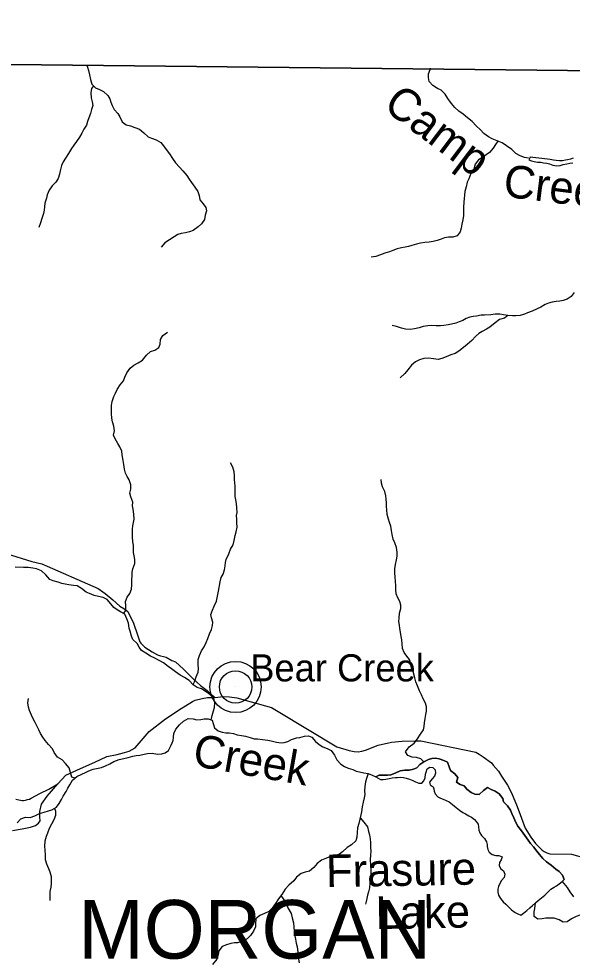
# Model space of a CAD drawing. Extents: x 1624196 to 2029251, y 146837 to 440034.
# Drawn here: x 1804212 to 1812706, y 335419 to 349890 of the extents above; entities that cross this region are included whole.
import ezdxf

# ---------------------------------------------------------------- set-up
doc = ezdxf.new("R2010")
doc.units = 0
for name, color, linetype in [('GM_X_Adjacent_County', 7, 'Continuous'), ('GM_X_County', 7, 'Continuous'), ('GM_X_County_Road', 7, 'Continuous'), ('GM_X_Major_River', 7, 'Continuous'), ('GM_X_Minor_Lake', 7, 'Continuous'), ('GM_X_Minor_Lake_Text', 7, 'Continuous'), ('GM_X_Minor_River', 7, 'Continuous'), ('GM_X_Minor_River_Text', 7, 'Continuous'), ('GM_X_Township', 7, 'Continuous'), ('GM_X_Township_Road', 7, 'Continuous'), ('GM_X_Township_Text', 7, 'Continuous'), ('GM_X_Unincorporated', 7, 'Continuous'), ('GM_X_Unincorporated_Location', 7, 'Continuous'), ('GM_X_Unincorporated_Text', 7, 'Continuous')]:
    doc.layers.add(name, color=color, linetype=linetype)

msp = doc.modelspace()

# ---------------------------------------------------------------- linework, layer by layer
at = {"layer": 'GM_X_Adjacent_County'}
msp.add_lwpolyline([(1826336, 348649), (1819510, 348957), (1818598, 348960), (1813935, 349079), (1813587, 349087), (1795056, 349285), (1795014, 349286), (1790774, 349462), (1789921, 349486), (1783877, 349656), (1782423, 349710), (1777594, 349890)], dxfattribs=at)
at = {"layer": 'GM_X_County'}
msp.add_lwpolyline([(1777594, 349890), (1782423, 349710), (1783877, 349656), (1789921, 349486), (1790774, 349462), (1795014, 349286), (1795056, 349285), (1813587, 349087), (1813935, 349079), (1818598, 348960), (1819510, 348957), (1826336, 348649)], dxfattribs=at)
at = {"layer": 'GM_X_County_Road'}
for points in [[(1804164, 337906), (1804212, 337895), (1804262, 337886), (1804282, 337886), (1804313, 337891), (1804346, 337899), (1804375, 337909), (1804399, 337921), (1804532, 337993), (1804670, 338059), (1804808, 338144), (1804932, 338274), (1805160, 338376), (1805380, 338477), (1805560, 338561), (1805721, 338591), (1805836, 338623), (1805906, 338644), (1805997, 338693), (1806212, 338946), (1806463, 339141), (1806706, 339298), (1806876, 339407), (1806917, 339425), (1807027, 339455), (1807110, 339466), (1807222, 339468)], [(1807222, 339468), (1807353, 339481), (1807445, 339478), (1807559, 339463), (1808092, 339313), (1808194, 339255), (1809094, 338711), (1809282, 338654), (1809358, 338640), (1809422, 338636), (1809479, 338642), (1809532, 338660), (1809726, 338737), (1809931, 338780), (1810096, 338796), (1810305, 338805), (1810383, 338802), (1811226, 338629), (1811277, 338600), (1811338, 338557), (1811467, 338465), (1811496, 338431), (1811575, 338339), (1811622, 338258), (1811712, 338122), (1811777, 338003), (1811862, 337793), (1811931, 337616), (1811983, 337459), (1812071, 337325), (1812144, 337226), (1812244, 337122), (1812279, 337101), (1812318, 337080), (1812364, 337068), (1812697, 337061), (1812914, 337000)], [(1804115, 337425), (1804263, 337452), (1804391, 337479), (1804466, 337502), (1804514, 337536), (1804538, 337574), (1804535, 337636), (1804532, 337718), (1804561, 337832), (1804646, 337953), (1804808, 338144)]]:
    msp.add_lwpolyline(points, dxfattribs=at)
at = {"layer": 'GM_X_Major_River'}
msp.add_lwpolyline([(1812724, 347749), (1812680, 347737), (1812634, 347726), (1812604, 347722), (1812556, 347712), (1812510, 347711), (1812460, 347715), (1812420, 347719), (1812368, 347728), (1812326, 347734), (1812280, 347741), (1812240, 347745), (1812196, 347749), (1812148, 347754), (1812102, 347760), (1812062, 347764), (1812039, 347727), (1812083, 347710), (1812125, 347698), (1812175, 347689), (1812223, 347687), (1812267, 347681), (1812317, 347672), (1812359, 347662), (1812409, 347645), (1812471, 347635), (1812521, 347640), (1812569, 347652), (1812623, 347664), (1812672, 347673), (1812718, 347681)], dxfattribs=at)
at = {"layer": 'GM_X_Minor_Lake'}
for points in [[(1812553, 336643), (1812581, 336673), (1812560, 336737), (1812506, 336798), (1812454, 336834), (1812385, 336891), (1812311, 336944), (1812258, 336998), (1812204, 337055), (1812163, 337109), (1812111, 337174), (1812067, 337224), (1812032, 337277), (1811929, 337422), (1811872, 337492), (1811844, 337549), (1811809, 337619), (1811781, 337687), (1811760, 337738), (1811716, 337804), (1811653, 337867), (1811643, 337917), (1811586, 337988), (1811524, 338028), (1811462, 338057), (1811406, 338087), (1811344, 338038), (1811277, 337978), (1811213, 337981), (1811157, 338009), (1811090, 338060), (1811046, 338112), (1810986, 338133), (1810931, 338167), (1810949, 338237), (1810904, 338294), (1810840, 338348), (1810820, 338405), (1810791, 338473), (1810735, 338502), (1810667, 338524), (1810609, 338537), (1810551, 338531), (1810501, 338516), (1810431, 338482), (1810370, 338438), (1810322, 338387), (1810272, 338365), (1810203, 338352), (1810135, 338350), (1810065, 338343), (1809991, 338305), (1809922, 338278), (1809870, 338276), (1809798, 338277), (1809742, 338275), (1809692, 338252)], [(1809692, 338252), (1809764, 338211), (1809806, 338211), (1809848, 338214), (1809898, 338226), (1809944, 338234), (1809994, 338239), (1810024, 338241), (1810070, 338242), (1810118, 338240), (1810160, 338230), (1810210, 338213), (1810258, 338193), (1810302, 338174), (1810352, 338152), (1810398, 338154), (1810430, 338187), (1810451, 338233), (1810457, 338289), (1810463, 338323), (1810482, 338371), (1810522, 338399), (1810568, 338395), (1810604, 338356), (1810609, 338306), (1810593, 338260), (1810557, 338218), (1810518, 338169), (1810526, 338129), (1810570, 338098), (1810581, 338064), (1810587, 338030), (1810605, 337988), (1810646, 337941), (1810686, 337923), (1810728, 337906), (1810774, 337886), (1810818, 337866), (1810871, 337825), (1810923, 337779), (1810975, 337740), (1811027, 337704), (1811070, 337679), (1811118, 337653), (1811162, 337628), (1811208, 337596), (1811234, 337566), (1811261, 337523), (1811269, 337481), (1811274, 337433), (1811288, 337389), (1811316, 337349), (1811361, 337304), (1811393, 337250), (1811399, 337208), (1811402, 337178), (1811412, 337133), (1811434, 337093), (1811479, 337059), (1811533, 337042), (1811581, 337040), (1811631, 337019), (1811617, 336977), (1811590, 336932), (1811588, 336888), (1811608, 336843), (1811651, 336805), (1811673, 336755), (1811664, 336705), (1811620, 336657), (1811594, 336609), (1811575, 336567), (1811565, 336525), (1811564, 336479), (1811574, 336431), (1811604, 336380), (1811647, 336332), (1811689, 336292), (1811735, 336249), (1811776, 336209), (1811830, 336168), (1811870, 336146), (1811916, 336123), (1811960, 336157), (1812010, 336199), (1812055, 336238), (1812097, 336276), (1812144, 336314), (1812186, 336350), (1812236, 336391), (1812287, 336433), (1812327, 336471), (1812380, 336522), (1812428, 336554), (1812468, 336578), (1812509, 336605), (1812553, 336643)]]:
    msp.add_lwpolyline(points, dxfattribs=at)
at = {"layer": 'GM_X_Minor_River'}
for points in [[(1805251, 349186), (1805264, 349147), (1805280, 349095), (1805297, 349032), (1805311, 348960), (1805334, 348888), (1805388, 348833), (1805448, 348805), (1805513, 348772), (1805577, 348715), (1805609, 348663), (1805624, 348613), (1805646, 348560), (1805675, 348500), (1805733, 348438), (1805760, 348383), (1805798, 348311), (1805861, 348262), (1805925, 348246), (1805993, 348223), (1806065, 348194), (1806131, 348138), (1806196, 348079), (1806248, 348059), (1806322, 348032), (1806390, 347993), (1806431, 347941), (1806475, 347884), (1806522, 347818), (1806570, 347745), (1806619, 347679), (1806677, 347614), (1806728, 347558), (1806790, 347487), (1806827, 347429), (1806861, 347378), (1806912, 347306), (1806958, 347237), (1806979, 347177), (1806992, 347111), (1807042, 347048), (1807080, 346992), (1807093, 346941), (1807073, 346875), (1807060, 346809), (1807015, 346742), (1806963, 346698), (1806890, 346640), (1806834, 346617), (1806770, 346605), (1806706, 346596), (1806653, 346578), (1806597, 346541), (1806523, 346495), (1806454, 346448), (1806395, 346382)], [(1812038, 347753), (1811974, 347763), (1811906, 347784), (1811840, 347824), (1811778, 347883), (1811699, 347938), (1811631, 347986), (1811557, 348017), (1811480, 348046), (1811420, 348078), (1811352, 348131), (1811301, 348188), (1811231, 348246), (1811170, 348313), (1811102, 348372), (1811034, 348426), (1810967, 348471), (1810905, 348529), (1810854, 348592), (1810800, 348665), (1810759, 348731), (1810693, 348796), (1810641, 348820), (1810568, 348869), (1810512, 348927), (1810499, 348990), (1810501, 349044), (1810528, 349114), (1810529, 349134)], [(1805360, 348861), (1805328, 348820), (1805315, 348754), (1805322, 348679), (1805336, 348617), (1805345, 348557), (1805325, 348497), (1805310, 348439), (1805286, 348371), (1805267, 348313), (1805251, 348259), (1805210, 348195), (1805181, 348137), (1805145, 348072), (1805096, 348006), (1805056, 347952), (1805019, 347898), (1804975, 347824), (1804930, 347753), (1804893, 347695), (1804869, 347639), (1804846, 347557), (1804838, 347505), (1804815, 347439), (1804780, 347381), (1804724, 347324), (1804679, 347260), (1804647, 347188), (1804634, 347134), (1804613, 347060), (1804603, 347002), (1804600, 346952), (1804590, 346900), (1804567, 346826), (1804545, 346756), (1804520, 346688)], [(1811564, 348014), (1811531, 347961), (1811496, 347905), (1811438, 347840), (1811387, 347800), (1811319, 347754), (1811267, 347723), (1811218, 347657), (1811197, 347583), (1811153, 347515), (1811118, 347433), (1811093, 347382), (1811077, 347312), (1811060, 347238), (1811054, 347184), (1811047, 347133), (1811043, 347077), (1811040, 346999), (1811039, 346869), (1811026, 346805), (1811014, 346737), (1811003, 346677), (1810989, 346617), (1810940, 346557), (1810872, 346538), (1810808, 346536), (1810747, 346525), (1810693, 346505), (1810633, 346488), (1810573, 346470), (1810513, 346463), (1810447, 346453), (1810378, 346444), (1810316, 346432), (1810246, 346411), (1810196, 346393), (1810142, 346383), (1810087, 346376), (1810019, 346358), (1809955, 346335), (1809903, 346313), (1809830, 346292), (1809762, 346268), (1809690, 346239), (1809622, 346231)], [(1812738, 345687), (1812690, 345625), (1812629, 345587), (1812569, 345564), (1812519, 345556), (1812463, 345551), (1812399, 345541), (1812342, 345524), (1812292, 345504), (1812226, 345464), (1812171, 345437), (1812093, 345399), (1812023, 345374), (1811973, 345356), (1811906, 345335), (1811840, 345329), (1811790, 345328), (1811718, 345332), (1811652, 345347), (1811594, 345355), (1811524, 345354), (1811458, 345345), (1811358, 345341), (1811308, 345338), (1811239, 345324), (1811189, 345317), (1811133, 345307), (1811081, 345288), (1811029, 345260), (1810974, 345236), (1810920, 345215), (1810854, 345199), (1810804, 345190), (1810734, 345180), (1810684, 345175), (1810618, 345175), (1810547, 345182), (1810493, 345178), (1810419, 345165), (1810359, 345147), (1810287, 345130), (1810217, 345122), (1810147, 345127), (1810087, 345139), (1810007, 345166), (1809941, 345183)], [(1811717, 345333), (1811666, 345291), (1811591, 345273), (1811523, 345224), (1811444, 345154), (1811392, 345123), (1811324, 345091), (1811273, 345060), (1811223, 345012), (1811166, 344952), (1811092, 344891), (1811015, 344825), (1810964, 344786), (1810910, 344750), (1810846, 344728), (1810774, 344699), (1810707, 344673), (1810647, 344660), (1810579, 344670), (1810499, 344677), (1810427, 344672), (1810363, 344654), (1810300, 344625), (1810238, 344573), (1810183, 344501), (1810137, 344444), (1810064, 344376)], [(1805820, 340757), (1805852, 340806), (1805855, 340878), (1805847, 340944), (1805874, 341008), (1805917, 341064), (1805941, 341134), (1805948, 341200), (1805946, 341274), (1805949, 341340), (1805951, 341392), (1805964, 341444), (1805993, 341524), (1805993, 341586), (1805984, 341642), (1805972, 341693), (1805970, 341743), (1805971, 341809), (1805962, 341861), (1805956, 341933), (1805957, 341999), (1805955, 342053), (1805964, 342103), (1805974, 342157), (1805981, 342209), (1805977, 342282), (1805968, 342358), (1805954, 342412), (1805961, 342470), (1805931, 342549), (1805916, 342607), (1805933, 342665), (1805933, 342735), (1805904, 342809), (1805874, 342860), (1805847, 342912), (1805833, 342972), (1805826, 343048), (1805814, 343107), (1805799, 343197), (1805793, 343249), (1805762, 343317), (1805730, 343370), (1805691, 343440), (1805667, 343496), (1805678, 343564), (1805671, 343637), (1805649, 343699), (1805640, 343759), (1805636, 343827), (1805635, 343893), (1805635, 343954), (1805646, 344012), (1805671, 344090), (1805693, 344141), (1805722, 344199), (1805766, 344269), (1805817, 344333), (1805837, 344385), (1805872, 344455), (1805921, 344528), (1805975, 344574), (1806042, 344610), (1806112, 344649), (1806171, 344723), (1806233, 344784), (1806300, 344804), (1806360, 344841), (1806380, 344893), (1806387, 344965), (1806422, 345027), (1806492, 345077)], [(1806886, 339666), (1806906, 339707), (1806936, 339783), (1806965, 339859), (1806970, 339911), (1806966, 339969), (1806965, 340049), (1806985, 340115), (1807016, 340187), (1807055, 340245), (1807087, 340315), (1807112, 340375), (1807140, 340447), (1807169, 340513), (1807184, 340575), (1807190, 340625), (1807171, 340691), (1807159, 340745), (1807186, 340809), (1807210, 340869), (1807245, 340945), (1807262, 341023), (1807276, 341101), (1807302, 341245), (1807320, 341309), (1807347, 341361), (1807369, 341431), (1807378, 341489), (1807382, 341539), (1807395, 341589), (1807435, 341675), (1807462, 341744), (1807501, 341812), (1807519, 341880), (1807534, 341956), (1807549, 342010), (1807561, 342084), (1807560, 342150), (1807556, 342207), (1807555, 342261), (1807563, 342311), (1807556, 342379), (1807552, 342445), (1807543, 342503), (1807535, 342557), (1807534, 342610), (1807534, 342666), (1807533, 342716), (1807522, 342816), (1807522, 342878), (1807519, 342936), (1807497, 343005), (1807462, 343073)], [(1810431, 338482), (1810383, 338524), (1810315, 338545), (1810249, 338554), (1810183, 338576), (1810150, 338633), (1810206, 338708), (1810279, 338766), (1810332, 338834), (1810380, 338903), (1810425, 338973), (1810433, 339023), (1810438, 339079), (1810449, 339145), (1810461, 339207), (1810470, 339257), (1810472, 339325), (1810455, 339380), (1810421, 339450), (1810392, 339508), (1810362, 339569), (1810333, 339645), (1810307, 339711), (1810292, 339768), (1810273, 339848), (1810247, 339918), (1810230, 339985), (1810210, 340049), (1810169, 340105), (1810125, 340158), (1810104, 340222), (1810096, 340292), (1810089, 340352), (1810083, 340405), (1810070, 340473), (1810060, 340527), (1810053, 340581), (1810047, 340633), (1810048, 340685), (1810058, 340763), (1810075, 340835), (1810077, 340885), (1810060, 340944), (1810030, 341000), (1810005, 341058), (1809997, 341129), (1809998, 341185), (1809993, 341255), (1809987, 341315), (1809984, 341383), (1809982, 341443), (1809993, 341509), (1810009, 341581), (1810020, 341641), (1810022, 341699), (1810011, 341772), (1809982, 341844), (1809960, 341900), (1809941, 341969), (1809933, 342035), (1809920, 342101), (1809904, 342155), (1809887, 342206), (1809865, 342276), (1809860, 342348), (1809856, 342402), (1809855, 342456), (1809849, 342516), (1809844, 342567), (1809832, 342631), (1809797, 342703), (1809779, 342759), (1809772, 342814)], [(1807166, 339124), (1807178, 339194), (1807200, 339264), (1807213, 339314), (1807221, 339384), (1807206, 339456), (1807146, 339515), (1807085, 339557), (1807015, 339602), (1806949, 339621), (1806887, 339665), (1806824, 339730), (1806754, 339777), (1806690, 339811), (1806619, 339860), (1806555, 339906), (1806503, 339943), (1806430, 339998), (1806364, 340036), (1806288, 340075), (1806234, 340105), (1806161, 340148), (1806095, 340191), (1806059, 340241), (1806026, 340296), (1805964, 340358), (1805941, 340412), (1805919, 340485), (1805904, 340535), (1805895, 340607), (1805869, 340678), (1805838, 340746), (1805774, 340786), (1805722, 340815), (1805668, 340851), (1805623, 340904), (1805569, 340973), (1805506, 341003), (1805432, 341018), (1805366, 341034), (1805298, 341063), (1805246, 341087), (1805176, 341144), (1805105, 341183), (1805049, 341189), (1804977, 341196), (1804923, 341208), (1804871, 341221), (1804813, 341237), (1804741, 341260), (1804689, 341282), (1804628, 341351), (1804562, 341412), (1804484, 341444), (1804426, 341453), (1804354, 341463), (1804282, 341466), (1804154, 341467)], [(1805075, 338230), (1805027, 338246), (1805004, 338316), (1804986, 338388), (1804929, 338455), (1804879, 338509), (1804807, 338554), (1804752, 338623), (1804726, 338679), (1804665, 338746), (1804617, 338810), (1804582, 338861), (1804542, 338917), (1804519, 338969), (1804493, 339024), (1804460, 339084), (1804432, 339140), (1804405, 339199), (1804375, 339267), (1804360, 339319), (1804348, 339384), (1804359, 339452)], [(1804184, 337543), (1804243, 337607), (1804315, 337630), (1804387, 337624), (1804457, 337653), (1804530, 337685), (1804598, 337708), (1804666, 337726), (1804718, 337741), (1804789, 337783), (1804833, 337839), (1804868, 337900), (1804890, 337954), (1804939, 338022), (1804965, 338074), (1804992, 338128), (1805037, 338196), (1805103, 338255), (1805178, 338291), (1805236, 338314), (1805286, 338340), (1805352, 338367), (1805405, 338379), (1805481, 338394), (1805543, 338416), (1805607, 338451), (1805670, 338487), (1805754, 338518), (1805822, 338532), (1805889, 338545), (1805961, 338565), (1806013, 338576), (1806071, 338584), (1806137, 338597), (1806189, 338609), (1806259, 338612), (1806339, 338600), (1806408, 338603), (1806458, 338619), (1806510, 338654), (1806549, 338736), (1806580, 338806), (1806588, 338858), (1806592, 338914), (1806621, 338984), (1806676, 339048), (1806740, 339107), (1806811, 339145), (1806889, 339140), (1806943, 339126), (1807005, 339129), (1807055, 339141), (1807119, 339142), (1807181, 339118), (1807194, 339068), (1807214, 339001), (1807270, 338957), (1807333, 338934), (1807389, 338924), (1807443, 338925), (1807507, 338917), (1807565, 338896), (1807629, 338884), (1807691, 338875), (1807761, 338853), (1807825, 338834), (1807877, 338832), (1807951, 338825), (1808035, 338812), (1808087, 338800), (1808167, 338781), (1808237, 338772), (1808287, 338776), (1808341, 338794), (1808400, 338823), (1808476, 338849), (1808526, 338854), (1808598, 338872), (1808658, 338877), (1808712, 338857), (1808766, 338790), (1808821, 338744), (1808881, 338709), (1808947, 338683), (1809009, 338652), (1809058, 338581)], [(1809058, 338581), (1809094, 338509), (1809155, 338442), (1809209, 338408), (1809265, 338381), (1809339, 338361), (1809392, 338338), (1809444, 338326), (1809510, 338313), (1809574, 338299), (1809626, 338280), (1809692, 338252), (1809742, 338275), (1809798, 338277), (1809870, 338276), (1809922, 338278), (1809991, 338305), (1810065, 338343), (1810135, 338350), (1810203, 338352), (1810272, 338365), (1810322, 338387), (1810370, 338438), (1810431, 338482), (1810501, 338516), (1810551, 338531), (1810609, 338537), (1810667, 338524), (1810735, 338502), (1810791, 338473), (1810820, 338405), (1810840, 338348), (1810904, 338294), (1810949, 338237), (1810931, 338167), (1810986, 338133), (1811046, 338112), (1811090, 338060), (1811157, 338009), (1811213, 337981), (1811277, 337978), (1811344, 338038), (1811406, 338087), (1811462, 338057), (1811524, 338028), (1811586, 337988), (1811643, 337917), (1811653, 337867), (1811716, 337804), (1811760, 337738), (1811781, 337687), (1811809, 337619), (1811844, 337549), (1811872, 337492), (1811929, 337422), (1812032, 337277), (1812067, 337224), (1812111, 337174), (1812163, 337109), (1812204, 337055), (1812258, 336998), (1812311, 336944), (1812385, 336891), (1812454, 336834), (1812506, 336798), (1812560, 336737), (1812581, 336673), (1812553, 336643), (1812628, 336548), (1812672, 336482), (1812727, 336409)], [(1809572, 338299), (1809556, 338241), (1809535, 338171), (1809522, 338101), (1809518, 338033), (1809525, 337976), (1809513, 337926), (1809496, 337860), (1809480, 337790), (1809471, 337714), (1809463, 337664), (1809448, 337602), (1809429, 337534), (1809413, 337464), (1809408, 337394), (1809402, 337324), (1809383, 337268), (1809320, 337205), (1809252, 337165), (1809183, 337096), (1809133, 337060), (1809059, 337038), (1809005, 337033), (1808934, 337003), (1808860, 336970), (1808791, 336920), (1808741, 336855), (1808674, 336801), (1808606, 336784), (1808546, 336766), (1808475, 336711), (1808431, 336655), (1808356, 336585), (1808299, 336522), (1808249, 336444), (1808200, 336378), (1808153, 336304), (1808103, 336233), (1808050, 336183), (1807984, 336149), (1807913, 336122), (1807851, 336068), (1807844, 335994), (1807844, 335944), (1807815, 335880), (1807769, 335812), (1807716, 335763), (1807642, 335725), (1807571, 335702), (1807521, 335698), (1807467, 335691), (1807399, 335671), (1807333, 335642), (1807280, 335578), (1807270, 335520), (1807249, 335450), (1807184, 335370)], [(1804760, 337766), (1804772, 337723), (1804772, 337655), (1804747, 337587), (1804714, 337523), (1804676, 337455), (1804651, 337383), (1804631, 337331), (1804610, 337261), (1804605, 337187), (1804611, 337125), (1804616, 337053), (1804618, 336981), (1804635, 336914), (1804668, 336842), (1804688, 336790), (1804707, 336719), (1804709, 336667), (1804706, 336613), (1804704, 336557), (1804687, 336491), (1804685, 336421), (1804686, 336353)], [(1809452, 337619), (1809510, 337552), (1809563, 337483), (1809578, 337411), (1809594, 337359), (1809604, 337298), (1809611, 337234), (1809608, 337168), (1809614, 337102), (1809611, 337052), (1809607, 336976), (1809610, 336892), (1809614, 336839), (1809617, 336773), (1809612, 336691), (1809602, 336615), (1809593, 336545), (1809578, 336481), (1809566, 336431), (1809547, 336357), (1809533, 336293)], [(1808236, 336427), (1808272, 336374), (1808319, 336299), (1808341, 336237), (1808390, 336150), (1808406, 336082), (1808427, 336006), (1808434, 335947), (1808440, 335879), (1808449, 335809), (1808457, 335759), (1808470, 335697), (1808486, 335640), (1808495, 335562), (1808501, 335504), (1808506, 335452), (1808514, 335394)], [(1812952, 336211), (1812895, 336153), (1812823, 336126), (1812766, 336106), (1812694, 336067), (1812632, 336021), (1812567, 336016), (1812506, 336054), (1812432, 336077), (1812368, 336080), (1812300, 336078), (1812248, 336071), (1812179, 336063), (1812124, 336106), (1812124, 336174), (1812133, 336226), (1812146, 336316)]]:
    msp.add_lwpolyline(points, dxfattribs=at)
at = {"layer": 'GM_X_Township'}
msp.add_lwpolyline([(1795056, 349285), (1813587, 349087)], dxfattribs=at)
at = {"layer": 'GM_X_Township_Road'}
for points in [[(1801619, 342756), (1801664, 342725), (1802851, 342192), (1803008, 342088), (1803121, 341988), (1803222, 341926), (1804410, 341558), (1804566, 341521), (1805429, 341141), (1805536, 341066), (1805657, 340967), (1805761, 340870), (1805823, 340837), (1805887, 340788), (1805972, 340610), (1806033, 340431), (1806033, 340431)], [(1806033, 340431), (1806070, 340322), (1806085, 340301), (1806120, 340264), (1806147, 340240), (1806256, 340171), (1806342, 340121), (1806386, 340108), (1806434, 340096), (1806472, 340089), (1806561, 340038), (1806619, 340015), (1806741, 339905), (1806890, 339754), (1807002, 339654), (1807105, 339574), (1807222, 339468)]]:
    msp.add_lwpolyline(points, dxfattribs=at)
at = {"layer": 'GM_X_Unincorporated'}
for radius in [393, 249]:
    msp.add_circle((1807539, 339630), radius, dxfattribs=at)
at = {"layer": 'GM_X_Unincorporated_Location'}
msp.add_line((1807539, 339630), (1807539, 339630), dxfattribs=at)

# ---------------------------------------------------------------- texts
at = {"layer": 'GM_X_Minor_Lake_Text'}
for s, rotation, p in [('Frasure', 1.004, (1808931, 336555)), ('Lake', 1.0044, (1809692, 335911))]:
    msp.add_text(s, height=500, rotation=rotation, dxfattribs=at).set_placement(p)
at = {"layer": 'GM_X_Minor_River_Text'}
for s, rotation, p in [('Camp', 323.0016, (1809785, 348519)), ('Creek', 352.9995, (1811634, 347163)), ('Creek', 350.0031, (1806862, 338423))]:
    msp.add_text(s, height=500, rotation=rotation, dxfattribs=at).set_placement(p)
at = {"layer": 'GM_X_Township_Text'}
msp.add_text('MORGAN', height=900, rotation=0, dxfattribs=at).set_placement((1805126, 335458))
at = {"layer": 'GM_X_Unincorporated_Text'}
msp.add_text('Bear Creek', height=417, rotation=0, dxfattribs=at).set_placement((1807764, 339715))

doc.saveas('drawing.dxf')
